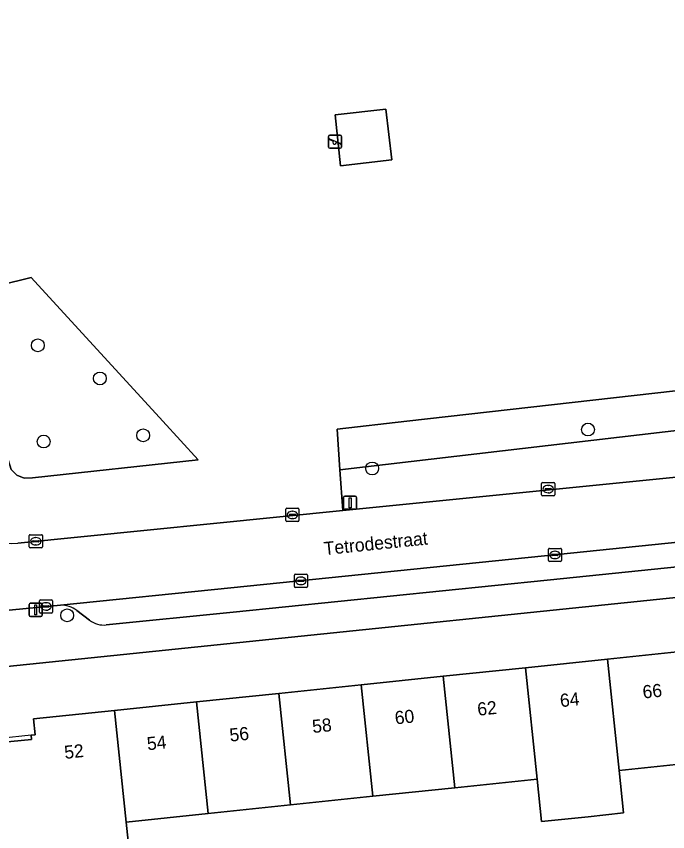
# Model space of a CAD drawing. Extents: x 160554 to 161248, y 385329 to 386506.
# Drawn here: x 160785.6 to 160835.3, y 385968.7 to 386030.9 of the extents above; entities that cross this region are included whole.
import ezdxf

# ---------------------------------------------------------------- set-up
doc = ezdxf.new("R2010")
doc.units = 0
for name, color, linetype in [('IMGEO_Boom', 7, 'Continuous'), ('IMGEO_Erf', 7, 'Continuous'), ('IMGEO_Groenvoorziening', 7, 'Continuous'), ('IMGEO_Kolk', 7, 'Continuous'), ('IMGEO_Lichtmast', 7, 'Continuous'), ('IMGEO_Openbare_ruimte_label', 7, 'Continuous'), ('IMGEO_Pand', 7, 'Continuous'), ('IMGEO_Pand_nummerreeks', 7, 'Continuous'), ('IMGEO_Pand_overbouw', 7, 'Continuous'), ('IMGEO_Parkeervlak_open', 7, 'Continuous'), ('IMGEO_Rijbaan_lokaal_open', 7, 'Continuous'), ('IMGEO_Speelvoorziening', 7, 'Continuous'), ('IMGEO_Terreindeel_open', 7, 'Continuous'), ('IMGEO_Voetpad_open', 7, 'Continuous')]:
    doc.layers.add(name, color=color, linetype=linetype)

msp = doc.modelspace()

# ---------------------------------------------------------------- linework, layer by layer
at = {"layer": 'IMGEO_Boom'}
for centre in [(160787.222, 386005.799), (160791.957, 386003.272), (160795.256, 385998.929), (160829.18, 385999.372), (160787.663, 385998.459), (160812.725, 385996.401), (160789.461, 385985.191)]:
    msp.add_circle(centre, 0.489, dxfattribs=at)
at = {"layer": 'IMGEO_Erf'}
for points in [[(160784.369, 385975.479), (160786.746, 385975.727), (160786.712, 385976.046), (160787.031, 385976.079), (160786.905, 385977.282), (160793.068, 385977.926), (160799.336, 385978.58), (160805.605, 385979.235), (160811.874, 385979.89), (160818.143, 385980.544), (160824.412, 385981.199), (160830.68, 385981.854), (160836.949, 385982.508), (160843.218, 385983.163), (160849.487, 385983.818), (160855.932, 385984.491), (160856.074, 385983.14), (160860.359, 385983.611), (160859.687, 385988.936), (160859.181, 385990.012)], [(160852.902, 385988.314), (160784.881, 385981.295)], [(160858.563, 385962.869), (160861.645, 385971.496), (160861.144, 385976.456), (160850.373, 385975.327), (160844.104, 385974.67), (160844.257, 385973.205), (160837.989, 385972.55), (160837.836, 385974.012), (160831.567, 385973.355), (160831.906, 385970.111), (160829.189, 385969.828), (160825.637, 385969.458), (160825.299, 385972.698)], [(160825.299, 385972.698), (160819.03, 385972.041), (160812.762, 385971.384), (160806.493, 385970.726), (160800.225, 385970.069), (160793.956, 385969.412), (160794.61, 385963.139), (160791.735, 385962.839), (160791.328, 385966.744), (160788.26, 385966.424), (160785.028, 385966.087)]]:
    msp.add_lwpolyline(points, dxfattribs=at)
at = {"layer": 'IMGEO_Groenvoorziening'}
for points in [[(160810.32, 386019.488), (160809.892, 386023.386), (160813.758, 386023.83), (160814.222, 386019.955)], [(160786.172, 385995.662), (160786.81, 385995.691), (160799.456, 385997.062), (160796.764, 386000), (160786.714, 386010.968), (160784.34, 386010.384), (160783.514, 386008.454), (160784.593, 386000), (160784.969, 385997.05), (160785.189, 385996.327), (160785.61, 385995.89)], [(160796.764, 386000), (160799.456, 385997.062), (160786.81, 385995.691), (160786.172, 385995.662), (160785.61, 385995.89), (160785.189, 385996.327), (160784.969, 385997.05), (160784.593, 386000), (160783.514, 386008.454), (160784.34, 386010.384), (160786.714, 386010.968)], [(160810.482, 385993.187), (160850.396, 385997.184), (160849.325, 386000), (160849.009, 386000.831), (160810.264, 385996.293)]]:
    msp.add_lwpolyline(points, close=True, dxfattribs=at)
for points in [[(160785.698, 385990.705), (160810.482, 385993.187), (160810.264, 385996.293), (160810.045, 385999.398), (160815.371, 386000), (160837.444, 386002.495), (160841.108, 386007.247)], [(160841.108, 386007.247), (160837.444, 386002.495), (160815.371, 386000), (160810.045, 385999.398), (160810.264, 385996.293), (160849.009, 386000.831)]]:
    msp.add_lwpolyline(points, dxfattribs=at)
msp.add_arc((160785.19, 385995.612), 4.934, 186.17186, 275.90952, dxfattribs=at)
at = {"layer": 'IMGEO_Kolk'}
for p, q in [((160825.651, 385994.399), (160825.651, 385995.251)), ((160825.726, 385995.325), (160826.578, 385995.325)), ((160826.139, 385995.105), (160826.164, 385995.105)), ((160826.652, 385995.251), (160826.652, 385994.399)), ((160825.91, 385994.819), (160825.91, 385994.831)), ((160826.348, 385994.782), (160825.95, 385994.782)), ((160825.953, 385994.868), (160826.351, 385994.868)), ((160826.162, 385994.545), (160826.137, 385994.545)), ((160826.394, 385994.831), (160826.394, 385994.819)), ((160826.578, 385994.325), (160825.726, 385994.325)), ((160806.139, 385992.434), (160806.139, 385993.286)), ((160806.214, 385993.36), (160807.066, 385993.36)), ((160807.14, 385993.286), (160807.14, 385992.434)), ((160806.398, 385992.854), (160806.398, 385992.866)), ((160806.836, 385992.817), (160806.438, 385992.817)), ((160806.441, 385992.903), (160806.839, 385992.903)), ((160806.65, 385992.58), (160806.625, 385992.58)), ((160806.627, 385993.14), (160806.652, 385993.14)), ((160806.882, 385992.866), (160806.882, 385992.854)), ((160807.066, 385992.36), (160806.214, 385992.36)), ((160786.643, 385991.348), (160787.495, 385991.348)), ((160786.568, 385990.422), (160786.568, 385991.274)), ((160786.827, 385990.842), (160786.827, 385990.854)), ((160787.265, 385990.805), (160786.867, 385990.805)), ((160786.87, 385990.891), (160787.268, 385990.891)), ((160787.056, 385991.128), (160787.081, 385991.128)), ((160787.311, 385990.854), (160787.311, 385990.842)), ((160787.569, 385991.274), (160787.569, 385990.422)), ((160787.495, 385990.348), (160786.643, 385990.348)), ((160787.079, 385990.568), (160787.054, 385990.568)), ((160826.163, 385989.38), (160826.163, 385990.232)), ((160826.238, 385990.306), (160827.09, 385990.306)), ((160826.651, 385990.086), (160826.676, 385990.086)), ((160827.164, 385990.232), (160827.164, 385989.38)), ((160826.422, 385989.8), (160826.422, 385989.812)), ((160826.86, 385989.763), (160826.462, 385989.763)), ((160826.465, 385989.849), (160826.863, 385989.849)), ((160826.674, 385989.526), (160826.649, 385989.526)), ((160826.906, 385989.812), (160826.906, 385989.8)), ((160827.09, 385989.306), (160826.238, 385989.306)), ((160806.787, 385987.4), (160806.787, 385988.252)), ((160806.862, 385988.326), (160807.714, 385988.326)), ((160807.788, 385988.252), (160807.788, 385987.4)), ((160807.046, 385987.82), (160807.046, 385987.832)), ((160807.484, 385987.783), (160807.086, 385987.783)), ((160807.089, 385987.869), (160807.487, 385987.869)), ((160807.275, 385988.106), (160807.3, 385988.106)), ((160807.53, 385987.832), (160807.53, 385987.82)), ((160807.714, 385987.326), (160806.862, 385987.326)), ((160807.298, 385987.546), (160807.273, 385987.546)), ((160787.418, 385986.371), (160788.27, 385986.371)), ((160787.343, 385985.445), (160787.343, 385986.297)), ((160787.602, 385985.865), (160787.602, 385985.877)), ((160788.04, 385985.828), (160787.642, 385985.828)), ((160787.645, 385985.914), (160788.043, 385985.914)), ((160787.831, 385986.151), (160787.856, 385986.151)), ((160788.086, 385985.877), (160788.086, 385985.865)), ((160788.344, 385986.297), (160788.344, 385985.445)), ((160788.27, 385985.371), (160787.418, 385985.371)), ((160787.854, 385985.591), (160787.829, 385985.591))]:
    msp.add_line(p, q, dxfattribs=at)
for points in [[(160825.651, 385994.399), (160825.651, 385995.251)], [(160825.726, 385995.325), (160826.578, 385995.325)], [(160826.652, 385995.251), (160826.652, 385994.399)], [(160826.578, 385994.325), (160825.726, 385994.325)], [(160806.139, 385992.434), (160806.139, 385993.286)], [(160806.214, 385993.36), (160807.066, 385993.36)], [(160807.14, 385993.286), (160807.14, 385992.434)], [(160807.066, 385992.36), (160806.214, 385992.36)], [(160786.643, 385991.348), (160787.495, 385991.348)], [(160786.568, 385990.422), (160786.568, 385991.274)], [(160787.569, 385991.274), (160787.569, 385990.422)], [(160787.495, 385990.348), (160786.643, 385990.348)], [(160826.163, 385989.38), (160826.163, 385990.232)], [(160826.238, 385990.306), (160827.09, 385990.306)], [(160827.164, 385990.232), (160827.164, 385989.38)], [(160827.09, 385989.306), (160826.238, 385989.306)], [(160806.787, 385987.4), (160806.787, 385988.252)], [(160806.862, 385988.326), (160807.714, 385988.326)], [(160807.788, 385988.252), (160807.788, 385987.4)], [(160807.714, 385987.326), (160806.862, 385987.326)], [(160787.418, 385986.371), (160788.27, 385986.371)], [(160787.343, 385985.445), (160787.343, 385986.297)], [(160788.344, 385986.297), (160788.344, 385985.445)], [(160788.27, 385985.371), (160787.418, 385985.371)]]:
    msp.add_lwpolyline(points, dxfattribs=at)
for centre, radius, start, end in [((160825.728, 385995.249), 0.0765, 91.55205, 178.44795), ((160825.728, 385995.249), 0.0765, 91.55205, 178.44795), ((160826.576, 385995.249), 0.0765, 1.55205, 88.44795), ((160826.576, 385995.249), 0.0765, 1.55205, 88.44795), ((160825.95, 385994.828), 0.0403, 85.87752, 175.75265), ((160825.947, 385994.818), 0.0366, 178.93798, 274.71019), ((160826.351, 385994.825), 0.043, 264.86636, 352.45326), ((160826.355, 385994.83), 0.0386, 1.73085, 96.63898), ((160825.728, 385994.401), 0.0765, 181.55205, 268.44795), ((160825.728, 385994.401), 0.0765, 181.55205, 268.44795), ((160826.576, 385994.401), 0.0765, 271.55205, 358.44795), ((160826.576, 385994.401), 0.0765, 271.55205, 358.44795), ((160806.216, 385993.284), 0.0765, 91.55205, 178.44795), ((160806.216, 385993.284), 0.0765, 91.55205, 178.44795), ((160807.064, 385993.284), 0.0765, 1.55205, 88.44795), ((160807.064, 385993.284), 0.0765, 1.55205, 88.44795), ((160806.438, 385992.863), 0.0403, 85.87752, 175.75265), ((160806.435, 385992.853), 0.0366, 178.93798, 274.71019), ((160806.839, 385992.86), 0.043, 264.86636, 352.45326), ((160806.843, 385992.865), 0.0386, 1.73085, 96.63898), ((160806.216, 385992.436), 0.0765, 181.55205, 268.44795), ((160806.216, 385992.436), 0.0765, 181.55205, 268.44795), ((160807.064, 385992.436), 0.0765, 271.55205, 358.44795), ((160807.064, 385992.436), 0.0765, 271.55205, 358.44795), ((160786.645, 385991.272), 0.0765, 91.55205, 178.44795), ((160786.645, 385991.272), 0.0765, 91.55205, 178.44795), ((160787.493, 385991.272), 0.0765, 1.55205, 88.44795), ((160787.493, 385991.272), 0.0765, 1.55205, 88.44795), ((160786.867, 385990.851), 0.0403, 85.87752, 175.75265), ((160786.864, 385990.841), 0.0366, 178.93798, 274.71019), ((160787.268, 385990.848), 0.043, 264.86636, 352.45326), ((160787.272, 385990.853), 0.0386, 1.73085, 96.63898), ((160786.645, 385990.424), 0.0765, 181.55205, 268.44795), ((160786.645, 385990.424), 0.0765, 181.55205, 268.44795), ((160787.493, 385990.424), 0.0765, 271.55205, 358.44795), ((160787.493, 385990.424), 0.0765, 271.55205, 358.44795), ((160826.24, 385990.23), 0.0765, 91.55205, 178.44795), ((160826.24, 385990.23), 0.0765, 91.55205, 178.44795), ((160827.088, 385990.23), 0.0765, 1.55205, 88.44795), ((160827.088, 385990.23), 0.0765, 1.55205, 88.44795), ((160826.462, 385989.809), 0.0403, 85.87752, 175.75265), ((160826.459, 385989.799), 0.0366, 178.93798, 274.71019), ((160826.863, 385989.806), 0.043, 264.86636, 352.45326), ((160826.867, 385989.811), 0.0386, 1.73085, 96.63898), ((160826.24, 385989.382), 0.0765, 181.55205, 268.44795), ((160826.24, 385989.382), 0.0765, 181.55205, 268.44795), ((160827.088, 385989.382), 0.0765, 271.55205, 358.44795), ((160827.088, 385989.382), 0.0765, 271.55205, 358.44795), ((160806.864, 385988.25), 0.0765, 91.55205, 178.44795), ((160806.864, 385988.25), 0.0765, 91.55205, 178.44795), ((160807.712, 385988.25), 0.0765, 1.55205, 88.44795), ((160807.712, 385988.25), 0.0765, 1.55205, 88.44795), ((160807.086, 385987.829), 0.0403, 85.87752, 175.75265), ((160807.083, 385987.819), 0.0366, 178.93798, 274.71019), ((160807.487, 385987.826), 0.043, 264.86636, 352.45326), ((160807.491, 385987.831), 0.0386, 1.73085, 96.63898), ((160806.864, 385987.402), 0.0765, 181.55205, 268.44795), ((160806.864, 385987.402), 0.0765, 181.55205, 268.44795), ((160807.712, 385987.402), 0.0765, 271.55205, 358.44795), ((160807.712, 385987.402), 0.0765, 271.55205, 358.44795), ((160787.42, 385986.295), 0.0765, 91.55205, 178.44795), ((160787.42, 385986.295), 0.0765, 91.55205, 178.44795), ((160788.268, 385986.295), 0.0765, 1.55205, 88.44795), ((160788.268, 385986.295), 0.0765, 1.55205, 88.44795), ((160787.642, 385985.874), 0.0403, 85.87752, 175.75265), ((160787.639, 385985.864), 0.0366, 178.93798, 274.71019), ((160788.043, 385985.871), 0.043, 264.86636, 352.45326), ((160788.047, 385985.876), 0.0386, 1.73085, 96.63898), ((160787.42, 385985.447), 0.0765, 181.55205, 268.44795), ((160787.42, 385985.447), 0.0765, 181.55205, 268.44795), ((160788.268, 385985.447), 0.0765, 271.55205, 358.44795), ((160788.268, 385985.447), 0.0765, 271.55205, 358.44795)]:
    msp.add_arc(centre, radius, start, end, dxfattribs=at)
for centre, major_axis, ratio, start_param, end_param in [((160826.138, 385994.825), (-0.387, 0.002), 0.722429, 4.712389, 7.853982), ((160826.163, 385994.825), (-0.39, 0.002), 0.717154, 1.570796, 4.712389), ((160806.626, 385992.86), (-0.387, 0.002), 0.722429, 4.712389, 7.853982), ((160806.651, 385992.86), (-0.39, 0.002), 0.717154, 1.570796, 4.712389), ((160787.055, 385990.848), (-0.387, 0.002), 0.722429, 4.712389, 7.853982), ((160787.08, 385990.848), (-0.39, 0.002), 0.717154, 1.570796, 4.712389), ((160826.65, 385989.806), (-0.387, 0.002), 0.722429, 4.712389, 7.853982), ((160826.675, 385989.806), (-0.39, 0.002), 0.717154, 1.570796, 4.712389), ((160807.274, 385987.826), (-0.387, 0.002), 0.722429, 4.712389, 7.853982), ((160807.299, 385987.826), (-0.39, 0.002), 0.717154, 1.570796, 4.712389), ((160787.83, 385985.871), (-0.387, 0.002), 0.722429, 4.712389, 7.853982), ((160787.855, 385985.871), (-0.39, 0.002), 0.717154, 1.570796, 4.712389)]:
    msp.add_ellipse(centre, major_axis=major_axis, ratio=ratio, start_param=start_param, end_param=end_param, dxfattribs=at)
at = {"layer": 'IMGEO_Lichtmast'}
for p, q in [((160810.542, 385993.385), (160810.542, 385994.185)), ((160810.542, 385994.185), (160810.542, 385993.385)), ((160810.642, 385994.285), (160811.432, 385994.285)), ((160811.432, 385994.285), (160810.642, 385994.285)), ((160811.532, 385994.185), (160811.532, 385993.385)), ((160811.532, 385993.385), (160811.532, 385994.185)), ((160811.432, 385993.285), (160810.642, 385993.285)), ((160810.642, 385993.285), (160811.432, 385993.285)), ((160786.564, 385985.213), (160786.564, 385986.013)), ((160786.564, 385986.013), (160786.564, 385985.213)), ((160786.664, 385986.113), (160787.454, 385986.113)), ((160787.454, 385986.113), (160786.664, 385986.113)), ((160787.554, 385986.013), (160787.554, 385985.213)), ((160787.554, 385985.213), (160787.554, 385986.013)), ((160787.454, 385985.113), (160786.664, 385985.113)), ((160786.664, 385985.113), (160787.454, 385985.113))]:
    msp.add_line(p, q, dxfattribs=at)
for points in [[(160810.962, 385994.16), (160811.112, 385994.16), (160811.112, 385993.41), (160810.962, 385993.41), (160810.962, 385994.16)], [(160786.984, 385985.988), (160787.134, 385985.988), (160787.134, 385985.238), (160786.984, 385985.238), (160786.984, 385985.988)]]:
    msp.add_lwpolyline(points, dxfattribs=at)
for centre, start, end in [((160810.642, 385994.185), 90, 180), ((160810.642, 385994.185), 90, 180), ((160811.432, 385994.185), 0, 90), ((160811.432, 385994.185), 360, 90), ((160810.642, 385993.385), 180, 270), ((160810.642, 385993.385), 180, 270), ((160811.432, 385993.385), 270, 0), ((160811.432, 385993.385), 270, 0), ((160786.664, 385986.013), 90, 180), ((160786.664, 385986.013), 90, 180), ((160787.454, 385986.013), 0, 90), ((160787.454, 385986.013), 360, 90), ((160786.664, 385985.213), 180, 270), ((160786.664, 385985.213), 180, 270), ((160787.454, 385985.213), 270, 0), ((160787.454, 385985.213), 270, 0)]:
    msp.add_arc(centre, 0.1, start, end, dxfattribs=at)
at = {"layer": 'IMGEO_Pand'}
for points in [[(160831.567, 385973.355), (160837.836, 385974.012), (160836.949, 385982.508), (160830.68, 385981.854)], [(160830.68, 385981.854), (160824.412, 385981.199), (160825.299, 385972.698), (160825.637, 385969.458), (160829.189, 385969.828), (160831.906, 385970.111), (160831.567, 385973.355)], [(160819.03, 385972.041), (160825.299, 385972.698), (160824.412, 385981.199), (160818.143, 385980.544)], [(160818.143, 385980.544), (160811.874, 385979.89), (160812.762, 385971.384), (160819.03, 385972.041)], [(160811.874, 385979.89), (160805.605, 385979.235), (160806.493, 385970.726), (160812.762, 385971.384)], [(160800.225, 385970.069), (160806.493, 385970.726), (160805.605, 385979.235), (160799.336, 385978.58)], [(160793.956, 385969.412), (160800.225, 385970.069), (160799.336, 385978.58), (160793.068, 385977.926)], [(160784.017, 385975.764), (160785.028, 385966.087), (160788.26, 385966.424), (160791.328, 385966.744), (160791.735, 385962.839), (160794.61, 385963.139), (160793.956, 385969.412), (160793.068, 385977.926), (160786.905, 385977.282), (160787.031, 385976.079), (160786.712, 385976.046), (160786.746, 385975.727), (160784.369, 385975.479), (160784.335, 385975.797)]]:
    msp.add_lwpolyline(points, close=True, dxfattribs=at)
at = {"layer": 'IMGEO_Pand_overbouw'}
msp.add_lwpolyline([(160786.712, 385976.046), (160784.335, 385975.797), (160784.369, 385975.479), (160786.746, 385975.727)], close=True, dxfattribs=at)
at = {"layer": 'IMGEO_Parkeervlak_open'}
for points in [[(160847.456, 385991.944), (160825.874, 385989.726), (160801.932, 385987.281), (160788.954, 385985.976)], [(160792.445, 385984.458), (160802.12, 385985.425), (160826.064, 385987.871), (160844.175, 385989.732)], [(160790.189, 385985.568), (160791.176, 385984.817)]]:
    msp.add_lwpolyline(points, dxfattribs=at)
for centre, radius, start, end in [((160788.978, 385983.975), 2.001, 52.75318, 90.68339), ((160792.266, 385986.246), 1.797, 232.6787, 275.7289)]:
    msp.add_arc(centre, radius, start, end, dxfattribs=at)
at = {"layer": 'IMGEO_Rijbaan_lokaal_open'}
for points in [[(160790.865, 386085.285), (160790.452, 386085.264), (160789.868, 386085.202), (160766.741, 386082.763), (160766.152, 386082.701), (160766.611, 386078.562), (160766.791, 386076.943), (160766.961, 386075.32), (160767.112, 386073.774), (160772.645, 386021.005), (160774.881, 386000), (160776.471, 385984.724), (160780.562, 385985.145), (160788.954, 385985.976), (160801.932, 385987.281), (160825.874, 385989.726), (160847.456, 385991.944), (160851.678, 385992.378)], [(160851.454, 385997.29), (160850.396, 385997.184), (160810.482, 385993.187), (160785.698, 385990.705)]]:
    msp.add_lwpolyline(points, dxfattribs=at)
msp.add_arc((160785.19, 385995.612), 4.934, 186.17186, 275.90952, dxfattribs=at)
at = {"layer": 'IMGEO_Speelvoorziening'}
for p, q in [((160809.488, 386021.835), (160810.278, 386021.835)), ((160810.278, 386021.835), (160809.488, 386021.835)), ((160809.388, 386020.935), (160809.388, 386021.735)), ((160809.388, 386021.735), (160809.388, 386020.935)), ((160809.771, 386021.363), (160809.432, 386021.5)), ((160809.457, 386021.56), (160810.333, 386021.207)), ((160810.309, 386021.147), (160809.969, 386021.284)), ((160810.378, 386021.735), (160810.378, 386020.935)), ((160810.378, 386020.935), (160810.378, 386021.735)), ((160810.278, 386020.835), (160809.488, 386020.835)), ((160809.488, 386020.835), (160810.278, 386020.835))]:
    msp.add_line(p, q, dxfattribs=at)
for centre, radius, start, end in [((160809.488, 386021.735), 0.1, 90, 180), ((160809.488, 386021.735), 0.1, 90, 180), ((160810.278, 386021.735), 0.1, 0, 90), ((160810.278, 386021.735), 0.1, 360, 90), ((160809.445, 386021.53), 0.0327, 68.07798, 248.07798), ((160809.85, 386021.273), 0.12, 130.99278, 5.16318), ((160810.321, 386021.177), 0.0327, 248.07798, 68.07798), ((160809.488, 386020.935), 0.1, 180, 270), ((160809.488, 386020.935), 0.1, 180, 270), ((160810.278, 386020.935), 0.1, 270, 0), ((160810.278, 386020.935), 0.1, 270, 0)]:
    msp.add_arc(centre, radius, start, end, dxfattribs=at)
at = {"layer": 'IMGEO_Terreindeel_open'}
msp.add_lwpolyline([(160810.32, 386019.488), (160814.222, 386019.955), (160813.758, 386023.83), (160809.892, 386023.386)], close=True, dxfattribs=at)
at = {"layer": 'IMGEO_Voetpad_open'}
for points in [[(160844.175, 385989.732), (160826.064, 385987.871), (160802.12, 385985.425), (160792.445, 385984.458)], [(160778.2, 385969.181), (160777.005, 385980.458), (160780.906, 385980.964), (160784.881, 385981.295), (160852.902, 385988.314)], [(160788.954, 385985.976), (160780.562, 385985.145), (160780.613, 385984.648), (160776.554, 385984.251), (160776.493, 385984.596), (160776.471, 385984.724), (160775.99, 385985.247), (160774.765, 385986.114)], [(160791.176, 385984.817), (160790.189, 385985.568)]]:
    msp.add_lwpolyline(points, dxfattribs=at)
for centre, radius, start, end in [((160788.978, 385983.975), 2.001, 52.75318, 90.68339), ((160792.266, 385986.246), 1.797, 232.6787, 275.7289)]:
    msp.add_arc(centre, radius, start, end, dxfattribs=at)

# ---------------------------------------------------------------- texts
at = {"layer": 'IMGEO_Openbare_ruimte_label'}
msp.add_text('Tetrodestraat', height=1, rotation=5.85309, dxfattribs=at).set_placement((160809.082, 385989.787))
at = {"layer": 'IMGEO_Pand_nummerreeks'}
for s, rotation, p in [('66', 5.96218, (160833.399, 385978.84)), ('64', 5.96449, (160827.098, 385978.182)), ('62', 5.96218, (160820.795, 385977.524)), ('60', 5.96218, (160814.5, 385976.866)), ('58', 5.96218, (160808.2, 385976.208)), ('56', 5.96218, (160801.896, 385975.55)), ('54', 5.96218, (160795.596, 385974.892)), ('52', 5.96218, (160789.292, 385974.234))]:
    msp.add_text(s, height=1, rotation=rotation, dxfattribs=at).set_placement(p)

doc.saveas('drawing.dxf')
